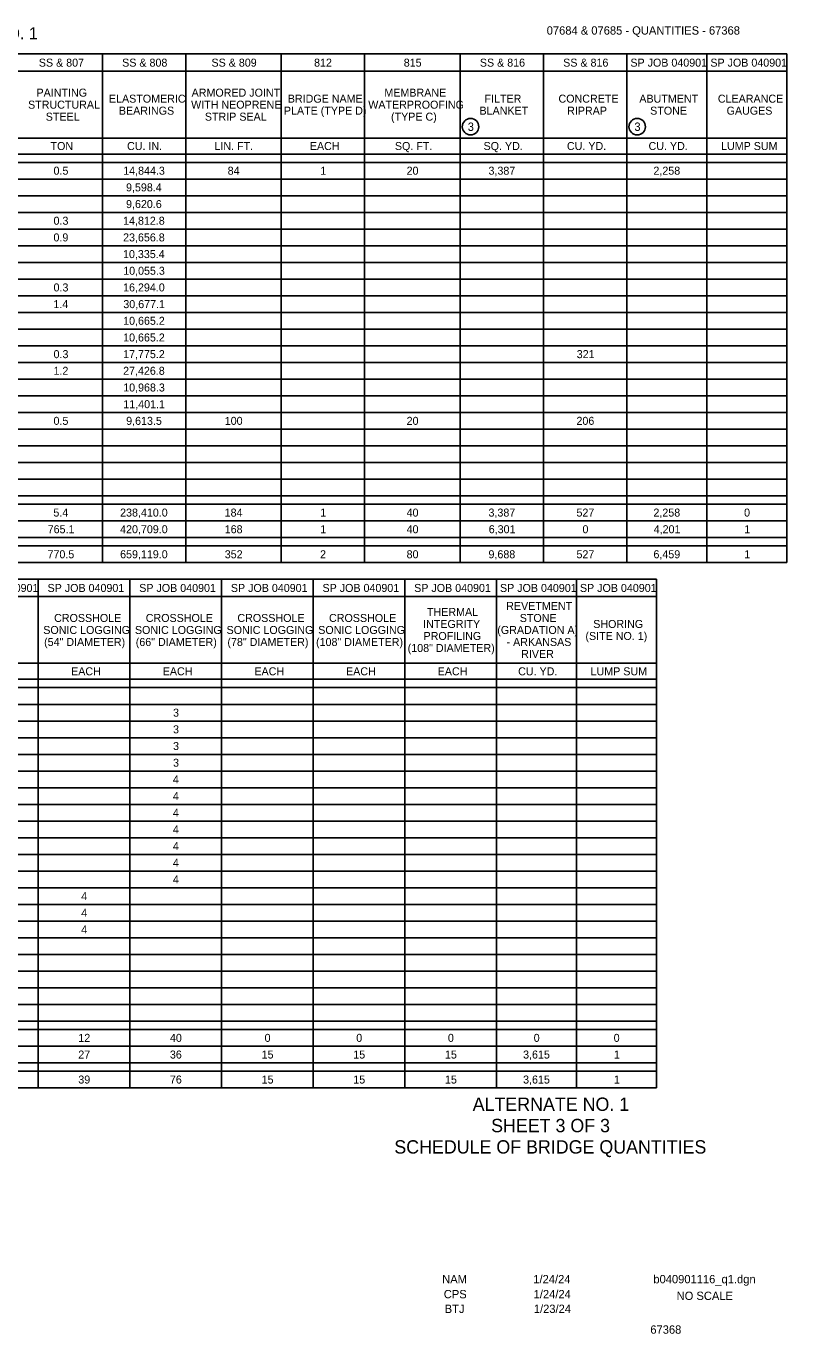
# Model space of a CAD drawing. Extents: x 0.06 to 1.38, y 0.04 to 0.85.
# Drawn here: x 0.907 to 1.382, y 0.037 to 0.854 of the extents above; entities that cross this region are included whole.
import ezdxf

# ---------------------------------------------------------------- set-up
doc = ezdxf.new("R2010")
doc.units = 0
for name, color, linetype in [('R_ROW', 7, 'Continuous'), ('R_Shade By Others', 7, 'Continuous'), ('R_Survey Control', 7, 'Continuous'), ('R_Wall', 7, 'Continuous')]:
    doc.layers.add(name, color=color, linetype=linetype)

msp = doc.modelspace()

# ---------------------------------------------------------------- linework, layer by layer
at = {"layer": 'R_Survey Control'}
for p, q in [((0.07508, 0.83695), (1.38207, 0.83695)), ((0.9543, 0.83695), (0.9543, 0.51924)), ((1.00638, 0.83695), (1.00638, 0.51924)), ((1.06595, 0.83695), (1.06595, 0.51924)), ((1.11803, 0.83695), (1.11803, 0.51924)), ((1.17793, 0.83695), (1.17793, 0.51924)), ((1.23001, 0.83695), (1.23001, 0.51924)), ((1.28209, 0.83695), (1.28209, 0.51924)), ((1.33207, 0.83695), (1.33207, 0.51924)), ((1.38207, 0.83695), (1.38207, 0.51924)), ((0.2593, 0.78445), (1.38207, 0.78445)), ((0.07508, 0.77445), (1.38207, 0.77445)), ((0.11154, 0.76924), (1.38207, 0.76924)), ((0.11154, 0.75883), (1.38207, 0.75883)), ((0.11154, 0.74841), (1.38207, 0.74841)), ((0.11154, 0.73799), (1.38207, 0.73799)), ((0.11154, 0.72758), (1.38207, 0.72758)), ((0.11154, 0.71716), (1.38207, 0.71716)), ((0.11154, 0.70674), (1.38207, 0.70674)), ((0.11154, 0.69633), (1.38207, 0.69633)), ((0.11154, 0.68591), (1.38207, 0.68591)), ((0.11154, 0.67549), (1.38207, 0.67549)), ((0.11154, 0.66508), (1.38207, 0.66508)), ((0.11154, 0.65466), (1.38207, 0.65466)), ((0.11154, 0.64424), (1.38207, 0.64424)), ((0.11154, 0.63383), (1.38207, 0.63383)), ((0.11154, 0.62341), (1.38207, 0.62341)), ((0.11154, 0.61299), (1.38207, 0.61299)), ((0.11154, 0.60258), (1.38207, 0.60258)), ((0.11154, 0.59216), (1.38207, 0.59216)), ((0.11154, 0.58174), (1.38207, 0.58174)), ((0.11154, 0.57133), (1.38207, 0.57133)), ((0.07508, 0.5557), (1.38207, 0.5557)), ((0.11154, 0.56091), (1.38207, 0.56091)), ((0.07508, 0.54529), (1.38207, 0.54529)), ((0.07508, 0.53487), (1.38207, 0.53487)), ((0.07508, 0.52966), (1.38207, 0.52966)), ((0.07508, 0.51924), (1.38207, 0.51924)), ((0.07508, 0.50883), (1.30054, 0.50883)), ((0.9141, 0.50883), (0.9141, 0.19112)), ((0.97139, 0.50883), (0.97139, 0.19112)), ((1.02868, 0.50883), (1.02868, 0.19112)), ((1.08598, 0.50883), (1.08598, 0.19112)), ((1.14327, 0.50883), (1.14327, 0.19112)), ((1.20056, 0.50883), (1.20056, 0.19112)), ((1.25055, 0.50883), (1.25055, 0.19112)), ((1.30054, 0.50883), (1.30054, 0.19112)), ((0.2593, 0.45633), (1.30054, 0.45633)), ((0.07508, 0.44633), (1.30054, 0.44633)), ((0.11154, 0.44112), (1.30054, 0.44112)), ((0.11154, 0.4307), (1.30054, 0.4307)), ((0.11154, 0.42029), (1.30054, 0.42029)), ((0.11154, 0.40987), (1.30054, 0.40987)), ((0.11154, 0.39945), (1.30054, 0.39945)), ((0.11154, 0.38904), (1.30054, 0.38904)), ((0.11154, 0.37862), (1.30054, 0.37862)), ((0.11154, 0.3682), (1.30054, 0.3682)), ((0.11154, 0.35779), (1.30054, 0.35779)), ((0.11154, 0.34737), (1.30054, 0.34737)), ((0.11154, 0.33695), (1.30054, 0.33695)), ((0.11154, 0.32654), (1.30054, 0.32654)), ((0.11154, 0.31612), (1.30054, 0.31612)), ((0.11154, 0.3057), (1.30054, 0.3057)), ((0.11154, 0.29529), (1.30054, 0.29529)), ((0.11154, 0.28487), (1.30054, 0.28487)), ((0.11154, 0.27445), (1.30054, 0.27445)), ((0.11154, 0.26404), (1.30054, 0.26404)), ((0.11154, 0.25362), (1.30054, 0.25362)), ((0.11154, 0.2432), (1.30054, 0.2432)), ((0.11154, 0.23279), (1.30054, 0.23279)), ((0.07508, 0.22758), (1.30054, 0.22758)), ((0.07508, 0.21716), (1.30054, 0.21716)), ((0.07508, 0.20674), (1.30054, 0.20674)), ((0.07508, 0.20154), (1.30054, 0.20154)), ((0.07508, 0.19112), (1.30054, 0.19112))]:
    msp.add_line(p, q, dxfattribs=at)
for points in [[(0.2593, 0.82612), (0.30758, 0.82612), (0.41883, 0.82612), (0.46733, 0.82612), (0.509, 0.82612), (0.60403, 0.82612), (0.64048, 0.82612), (0.68476, 0.82612), (0.72903, 0.82612), (0.79673, 0.82612), (0.84248, 0.82612), (0.89457, 0.82612), (0.99353, 0.82612), (1.05082, 0.82612), (1.11332, 0.82612), (1.24092, 0.82612), (1.249, 0.82612), (1.30109, 0.82612), (1.30109, 0.82612), (1.38207, 0.82612)], [(0.2593, 0.49799), (0.30758, 0.49799), (0.36154, 0.49799), (0.40321, 0.49799), (0.44487, 0.49799), (0.49175, 0.49799), (0.52821, 0.49799), (0.58029, 0.49799), (0.64019, 0.49799), (0.7079, 0.49799), (0.75998, 0.49799), (0.81206, 0.49799), (0.85894, 0.49799), (0.86623, 0.49799), (0.92873, 0.49799), (0.99644, 0.49799), (1.06415, 0.49799), (1.11623, 0.49799), (1.16831, 0.49799), (1.30054, 0.49799)]]:
    msp.add_lwpolyline(points, dxfattribs=at)
at = {"layer": 'R_Wall'}
for centre in [(1.18434, 0.79152), (1.2885, 0.79152)]:
    msp.add_circle(centre, 0.00515, dxfattribs=at)

# ---------------------------------------------------------------- texts
at = {"layer": 'R_ROW'}
msp.add_text('SCHEDULE OF BRIDGE QUANTITIES - JOB NO. 040901 - ALTERNATE NO. 1', height=0.0075, dxfattribs=at).set_placement((0.55601, 0.84612))
at = {"layer": 'R_Shade By Others'}
for s, height, p in [('07684 & 07685 - QUANTITIES - 67368', 0.0052083, (1.23195, 0.84904)), ('ALTERNATE NO. 1', 0.0083332, (1.18566, 0.17677)), ('SHEET 3 OF 3', 0.0083332, (1.1972, 0.16344)), ('SCHEDULE OF BRIDGE QUANTITIES', 0.0083332, (1.13669, 0.1501)), ('NAM', 0.005208, (1.1666, 0.06906)), ('1/24/24', 0.005208, (1.22357, 0.06906)), ('b040901116_q1.dgn', 0.0052083, (1.29862, 0.06906)), ('CPS', 0.005208, (1.1676, 0.05969)), ('1/24/24', 0.005208, (1.22378, 0.05969)), ('NO SCALE', 0.005208, (1.31316, 0.05864)), ('BTJ', 0.005208, (1.16819, 0.05052)), ('1/23/24', 0.005208, (1.22389, 0.05052)), ('67368', 0.005208, (1.29672, 0.03756))]:
    msp.add_text(s, height=height, dxfattribs=at).set_placement(p)
at = {"layer": 'R_Survey Control'}
for s, p in [('SS & 807', (0.91446, 0.82904)), ('SS & 808', (0.96655, 0.82904)), ('SS & 809', (1.02239, 0.82904)), ('812', (1.08651, 0.82904)), ('815', (1.14258, 0.82904)), ('SS & 816', (1.19016, 0.82904)), ('SS & 816', (1.24225, 0.82904)), ('SP JOB 040901', (1.28425, 0.82904)), ('SP JOB 040901', (1.33425, 0.82904)), ('PAINTING', (0.91301, 0.81029)), ('ELASTOMERIC', (0.95828, 0.80654)), ('ARMORED JOINT', (1.00997, 0.81029)), ('BRIDGE NAME', (1.07009, 0.80654)), ('MEMBRANE', (1.13047, 0.81029)), ('FILTER', (1.19306, 0.80654)), ('CONCRETE', (1.23931, 0.80654)), ('ABUTMENT', (1.28984, 0.80654)), ('CLEARANCE', (1.33894, 0.80654)), ('STRUCTURAL', (0.90772, 0.80279)), ('BEARINGS', (0.96449, 0.79904)), ('WITH NEOPRENE', (1.00965, 0.80279)), ('PLATE (TYPE D)', (1.06764, 0.79904)), ('WATERPROOFING', (1.1204, 0.80279)), ('(TYPE C)', (1.13463, 0.79529)), ('BLANKET', (1.18992, 0.79904)), ('RIPRAP', (1.24471, 0.79904)), ('STONE', (1.29661, 0.79904)), ('GAUGES', (1.34441, 0.79904)), ('STEEL', (0.91878, 0.79529)), ('STRIP SEAL', (1.01825, 0.79529)), ('TON', (0.92178, 0.77695)), ('CU. IN.', (0.96961, 0.77695)), ('LIN. FT.', (1.02424, 0.77695)), ('EACH', (1.08387, 0.77695)), ('SQ. FT.', (1.13705, 0.77695)), ('SQ. YD.', (1.19247, 0.77695)), ('CU. YD.', (1.24459, 0.77695)), ('CU. YD.', (1.29561, 0.77695)), ('LUMP SUM', (1.34093, 0.77695)), ('0.5', (0.92364, 0.76154)), ('14,844.3', (0.9672, 0.76154)), ('84', (1.0325, 0.76154)), ('1', (1.09039, 0.76154)), ('20', (1.14437, 0.76154)), ('3,387', (1.19555, 0.76154)), ('2,258', (1.29866, 0.76154)), ('9,598.4', (0.96897, 0.75112)), ('9,620.6', (0.96899, 0.7407)), ('0.3', (0.92366, 0.73029)), ('14,812.8', (0.96713, 0.73029)), ('0.9', (0.92361, 0.71987)), ('23,656.8', (0.96713, 0.71987)), ('10,335.4', (0.96709, 0.70945)), ('10,055.3', (0.9672, 0.69904)), ('0.3', (0.92366, 0.68862)), ('16,294.0', (0.96714, 0.68862)), ('1.4', (0.92355, 0.6782)), ('30,677.1', (0.96728, 0.6782)), ('10,665.2', (0.96716, 0.66779)), ('10,665.2', (0.96716, 0.65737)), ('0.3', (0.92366, 0.64695)), ('17,775.2', (0.96716, 0.64695)), ('321', (1.2507, 0.64695)), ('1.2', (0.92362, 0.63654)), ('27,426.8', (0.96713, 0.63654)), ('10,968.3', (0.9672, 0.62612)), ('11,401.1', (0.96728, 0.6157)), ('0.5', (0.92364, 0.60529)), ('9,613.5', (0.96906, 0.60529)), ('100', (1.03068, 0.60529)), ('20', (1.14437, 0.60529)), ('206', (1.25054, 0.60529)), ('5.4', (0.92355, 0.54799)), ('238,410.0', (0.96527, 0.54799)), ('184', (1.03062, 0.54799)), ('1', (1.09039, 0.54799)), ('40', (1.14437, 0.54799)), ('3,387', (1.19555, 0.54799)), ('527', (1.25055, 0.54799)), ('2,258', (1.29866, 0.54799)), ('0', (1.35533, 0.54799)), ('765.1', (0.91999, 0.53758)), ('420,709.0', (0.96527, 0.53758)), ('168', (1.03066, 0.53758)), ('1', (1.09039, 0.53758)), ('40', (1.14437, 0.53758)), ('6,301', (1.1957, 0.53758)), ('0', (1.25431, 0.53758)), ('4,201', (1.29882, 0.53758)), ('1', (1.35547, 0.53758)), ('770.5', (0.91989, 0.52195)), ('659,119.0', (0.96527, 0.52195)), ('352', (1.03069, 0.52195)), ('2', (1.09027, 0.52195)), ('80', (1.14437, 0.52195)), ('9,688', (1.19555, 0.52195)), ('527', (1.25055, 0.52195)), ('6,459', (1.29868, 0.52195)), ('1', (1.35547, 0.52195)), ('SP JOB 040901', (0.86628, 0.50091)), ('SP JOB 040901', (0.91992, 0.50091)), ('SP JOB 040901', (0.97721, 0.50091)), ('SP JOB 040901', (1.0345, 0.50091)), ('SP JOB 040901', (1.09179, 0.50091)), ('SP JOB 040901', (1.14909, 0.50091)), ('SP JOB 040901', (1.20273, 0.50091)), ('SP JOB 040901', (1.25271, 0.50091)), ('THERMAL', (1.15711, 0.48591)), ('REVETMENT', (1.20662, 0.48966)), ('CROSSHOLE', (0.92401, 0.48216)), ('CROSSHOLE', (0.9813, 0.48216)), ('CROSSHOLE', (1.03859, 0.48216)), ('CROSSHOLE', (1.09588, 0.48216)), ('INTEGRITY', (1.15468, 0.47841)), ('STONE', (1.21509, 0.48216)), ('SHORING', (1.26103, 0.47841)), ('SONIC LOGGING', (0.91724, 0.47466)), ('SONIC LOGGING', (0.97453, 0.47466)), ('SONIC LOGGING', (1.03182, 0.47466)), ('SONIC LOGGING', (1.08912, 0.47466)), ('PROFILING', (1.15496, 0.47091)), ('(GRADATION A)', (1.20106, 0.47466)), ('(SITE NO. 1)', (1.25616, 0.47091)), ('(54" DIAMETER)', (0.91776, 0.46716)), ('(66" DIAMETER)', (0.97505, 0.46716)), ('(78" DIAMETER)', (1.03235, 0.46716)), ('(108" DIAMETER)', (1.08776, 0.46716)), ('(108" DIAMETER)', (1.14505, 0.46341)), ('- ARKANSAS', (1.20685, 0.46716)), ('RIVER', (1.21597, 0.45966)), ('EACH', (0.93462, 0.44883)), ('EACH', (0.99191, 0.44883)), ('EACH', (1.04921, 0.44883)), ('EACH', (1.1065, 0.44883)), ('EACH', (1.16379, 0.44883)), ('CU. YD.', (1.21409, 0.44883)), ('LUMP SUM', (1.25939, 0.44883)), ('3', (0.99836, 0.42299)), ('3', (0.99836, 0.41258)), ('3', (0.99836, 0.40216)), ('3', (0.99836, 0.39174)), ('4', (0.99825, 0.38133)), ('4', (0.99825, 0.37091)), ('4', (0.99825, 0.36049)), ('4', (0.99825, 0.35008)), ('4', (0.99825, 0.33966)), ('4', (0.99825, 0.32924)), ('4', (0.99825, 0.31883)), ('4', (0.94096, 0.30841)), ('4', (0.94096, 0.29799)), ('4', (0.94096, 0.28758)), ('12', (0.93915, 0.21987)), ('40', (0.99642, 0.21987)), ('0', (1.05559, 0.21987)), ('0', (1.11288, 0.21987)), ('0', (1.17018, 0.21987)), ('0', (1.22382, 0.21987)), ('0', (1.2738, 0.21987)), ('27', (0.93912, 0.20945)), ('36', (0.9964, 0.20945)), ('15', (1.05376, 0.20945)), ('15', (1.11105, 0.20945)), ('15', (1.16834, 0.20945)), ('3,615', (1.21719, 0.20945)), ('1', (1.27394, 0.20945)), ('39', (0.93914, 0.19383)), ('76', (0.9964, 0.19383)), ('15', (1.05376, 0.19383)), ('15', (1.11105, 0.19383)), ('15', (1.16834, 0.19383)), ('3,615', (1.21719, 0.19383)), ('1', (1.27394, 0.19383))]:
    msp.add_text(s, height=0.005, dxfattribs=at).set_placement(p)
at = {"layer": 'R_Wall'}
for p in [(1.18258, 0.78892), (1.28675, 0.78892)]:
    msp.add_text('3', height=0.00521, dxfattribs=at).set_placement(p)

doc.saveas('drawing.dxf')
